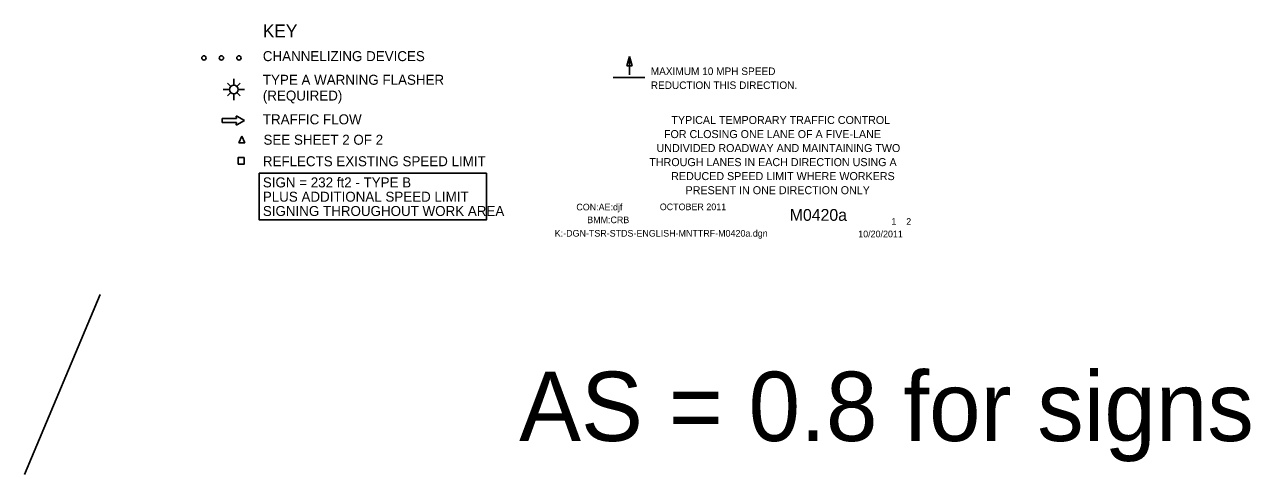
# Model space of a CAD drawing. Extents: x 16577 to 18475, y 5712 to 6909.
# Drawn here: x 16577 to 17718, y 5712 to 6131 of the extents above; entities that cross this region are included whole.
import ezdxf

# ---------------------------------------------------------------- set-up
doc = ezdxf.new("R2010")
doc.units = 0
for name, color, linetype in [('BORDER_SIGNAL_WO', 7, 'Continuous'), ('MT_SCRATCH_LEVEL_E', 7, 'Continuous'), ('TRAFFIC_SIGNS_PR', 7, 'Continuous'), ('TYPICAL_TEXT_DIMEN_EX', 7, 'Continuous'), ('TYPICAL_TEXT_DIMEN_PR', 7, 'Continuous')]:
    doc.layers.add(name, color=color, linetype=linetype)

msp = doc.modelspace()

# ---------------------------------------------------------------- linework, layer by layer
at = {"layer": 'MT_SCRATCH_LEVEL_E'}
for p, q in [((16774.2, 6045.4), (16774.5, 6043.6)), ((16774.2, 6045.4), (16774.5, 6043.6)), ((16782.1, 6041.7), (16774.9, 6045.8)), ((16782.1, 6041.7), (16774.9, 6045.8)), ((16774.5, 6043.6), (16761.2, 6043.6)), ((16761.2, 6043.6), (16761.2, 6039.8)), ((16774.5, 6043.6), (16761.2, 6043.6)), ((16761.2, 6043.6), (16761.2, 6039.8)), ((16761.2, 6039.8), (16774.5, 6039.8)), ((16761.2, 6039.8), (16774.5, 6039.8)), ((16774.5, 6039.8), (16774.2, 6038.1)), ((16774.5, 6039.8), (16774.2, 6038.1)), ((16774.9, 6037.6), (16782.1, 6041.7)), ((16774.9, 6037.6), (16782.1, 6041.7))]:
    msp.add_line(p, q, dxfattribs=at)
for centre, start, end in [((16774.7, 6045.4), 60.4248, 189.9638), ((16774.7, 6045.4), 60.4248, 189.9638), ((16774.7, 6038), 170.0362, 299.7731), ((16774.7, 6038), 170.0362, 299.7731)]:
    msp.add_arc(centre, 0.463, start, end, dxfattribs=at)
at = {"layer": 'TRAFFIC_SIGNS_PR'}
for p, q in [((16772.1, 6075), (16772.1, 6080.6)), ((16768.1, 6070.6), (16762.1, 6070.6)), ((16768.9, 6073.7), (16766.3, 6076.4)), ((16768.9, 6067.5), (16766.3, 6064.8)), ((16775.2, 6073.7), (16777.9, 6076.4)), ((16775.2, 6067.4), (16777.9, 6064.8)), ((16776, 6070.6), (16782.1, 6070.6)), ((16772.1, 6060.6), (16772.1, 6066.1))]:
    msp.add_line(p, q, dxfattribs=at)
for points in [[(16779.5, 6027.2), (16776.7, 6021)], [(16776.7, 6021), (16779.5, 6027.2)], [(16776.7, 6021), (16782.3, 6021)], [(16782.3, 6021), (16776.7, 6021)], [(16782.3, 6021), (16779.5, 6027.2)], [(16779.5, 6027.2), (16782.3, 6021)]]:
    msp.add_lwpolyline(points, dxfattribs=at)
msp.add_lwpolyline([(16776.1, 6001.1), (16781.7, 6001.1), (16781.7, 6007.2), (16776.1, 6007.2)], close=True, dxfattribs=at)
for centre, radius in [((16744.3, 6100), 2), ((16760.6, 6100), 2), ((16776.9, 6100), 2), ((16772.1, 6070.6), 3.94)]:
    msp.add_circle(centre, radius, dxfattribs=at)
at = {"layer": 'TYPICAL_TEXT_DIMEN_EX'}
msp.add_lwpolyline([(16795.8, 5992.6), (17007, 5992.6), (17007, 5949.3), (16795.8, 5949.3)], close=True, dxfattribs=at)
at = {"layer": 'TYPICAL_TEXT_DIMEN_PR'}
for p, q in [((17137.8, 6092.5), (17140.2, 6101.3)), ((17140.2, 6084.2), (17140.2, 6101.3)), ((17140.2, 6101.3), (17142.6, 6092.5)), ((17140.2, 6092.5), (17137.8, 6092.5)), ((17142.6, 6092.5), (17140.2, 6092.5)), ((17154.4, 6081.7), (17124.9, 6081.7)), ((16647.8, 5880), (16577.4, 5712.4))]:
    msp.add_line(p, q, dxfattribs=at)

# ---------------------------------------------------------------- texts
at = {"layer": 'BORDER_SIGNAL_WO'}
for s, height, p in [('TYPICAL TEMPORARY TRAFFIC CONTROL', 7.442, (17179.1, 6038.5)), ('FOR CLOSING ONE LANE OF A FIVE-LANE', 7.442, (17172.2, 6025.4)), ('UNDIVIDED ROADWAY AND MAINTAINING TWO', 7.442, (17165.3, 6012.4)), ('THROUGH LANES IN EACH DIRECTION USING A', 7.442, (17158.6, 5999.3)), ('REDUCED SPEED LIMIT WHERE WORKERS', 7.442, (17178.9, 5986.3)), ('PRESENT IN ONE DIRECTION ONLY', 7.442, (17192.3, 5973.2)), ('CON:AE:djf', 6.2, (17090.7, 5958.1)), ('    OCTOBER 2011    ', 6.2, (17159.1, 5958.3)), ('BMM:CRB   ', 6.2, (17100.8, 5946.2)), ('    M0420a   ', 11, (17272.9, 5948.4)), (' 1    2 ', 6.2, (17381.4, 5944.7)), ('K:-DGN-TSR-STDS-ENGLISH-MNTTRF-M0420a.dgn        ', 6.2, (17070.6, 5933.7)), ('10/20/2011    ', 6.2, (17352.9, 5933.1)), ('AS = 0.8 for signs', 64.512, (17037.5, 5743.5))]:
    msp.add_text(s, height=height, dxfattribs=at).set_placement(p)
at = {"layer": 'TYPICAL_TEXT_DIMEN_EX'}
for s, height, p in [('KEY', 12, (16799.1, 6119.1)), ('CHANNELIZING DEVICES', 9.3, (16799.1, 6097)), ('TYPE A WARNING FLASHER', 9.3, (16799.1, 6075)), ('(REQUIRED)', 9.3, (16799.1, 6060.3)), ('TRAFFIC FLOW', 9.3, (16799.1, 6038.2)), ('SEE SHEET 2 OF 2', 9.3, (16799.7, 6019.2)), ('REFLECTS EXISTING SPEED LIMIT', 9.3, (16799.1, 5999.2)), ('SIGN = 232 ft2 - TYPE B', 9.3, (16799.1, 5979.5)), ('PLUS ADDITIONAL SPEED LIMIT', 9.3, (16799.1, 5966.2)), ('SIGNING THROUGHOUT WORK AREA', 9.3, (16799.1, 5952.9))]:
    msp.add_text(s, height=height, dxfattribs=at).set_placement(p)
at = {"layer": 'TYPICAL_TEXT_DIMEN_PR'}
for s, p in [('MAXIMUM 10 MPH SPEED', (17159.9, 6084.1)), ('REDUCTION THIS DIRECTION.', (17159.9, 6071.1))]:
    msp.add_text(s, height=7, dxfattribs=at).set_placement(p)

doc.saveas('drawing.dxf')
